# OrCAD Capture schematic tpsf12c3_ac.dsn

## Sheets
1 Page1: size C
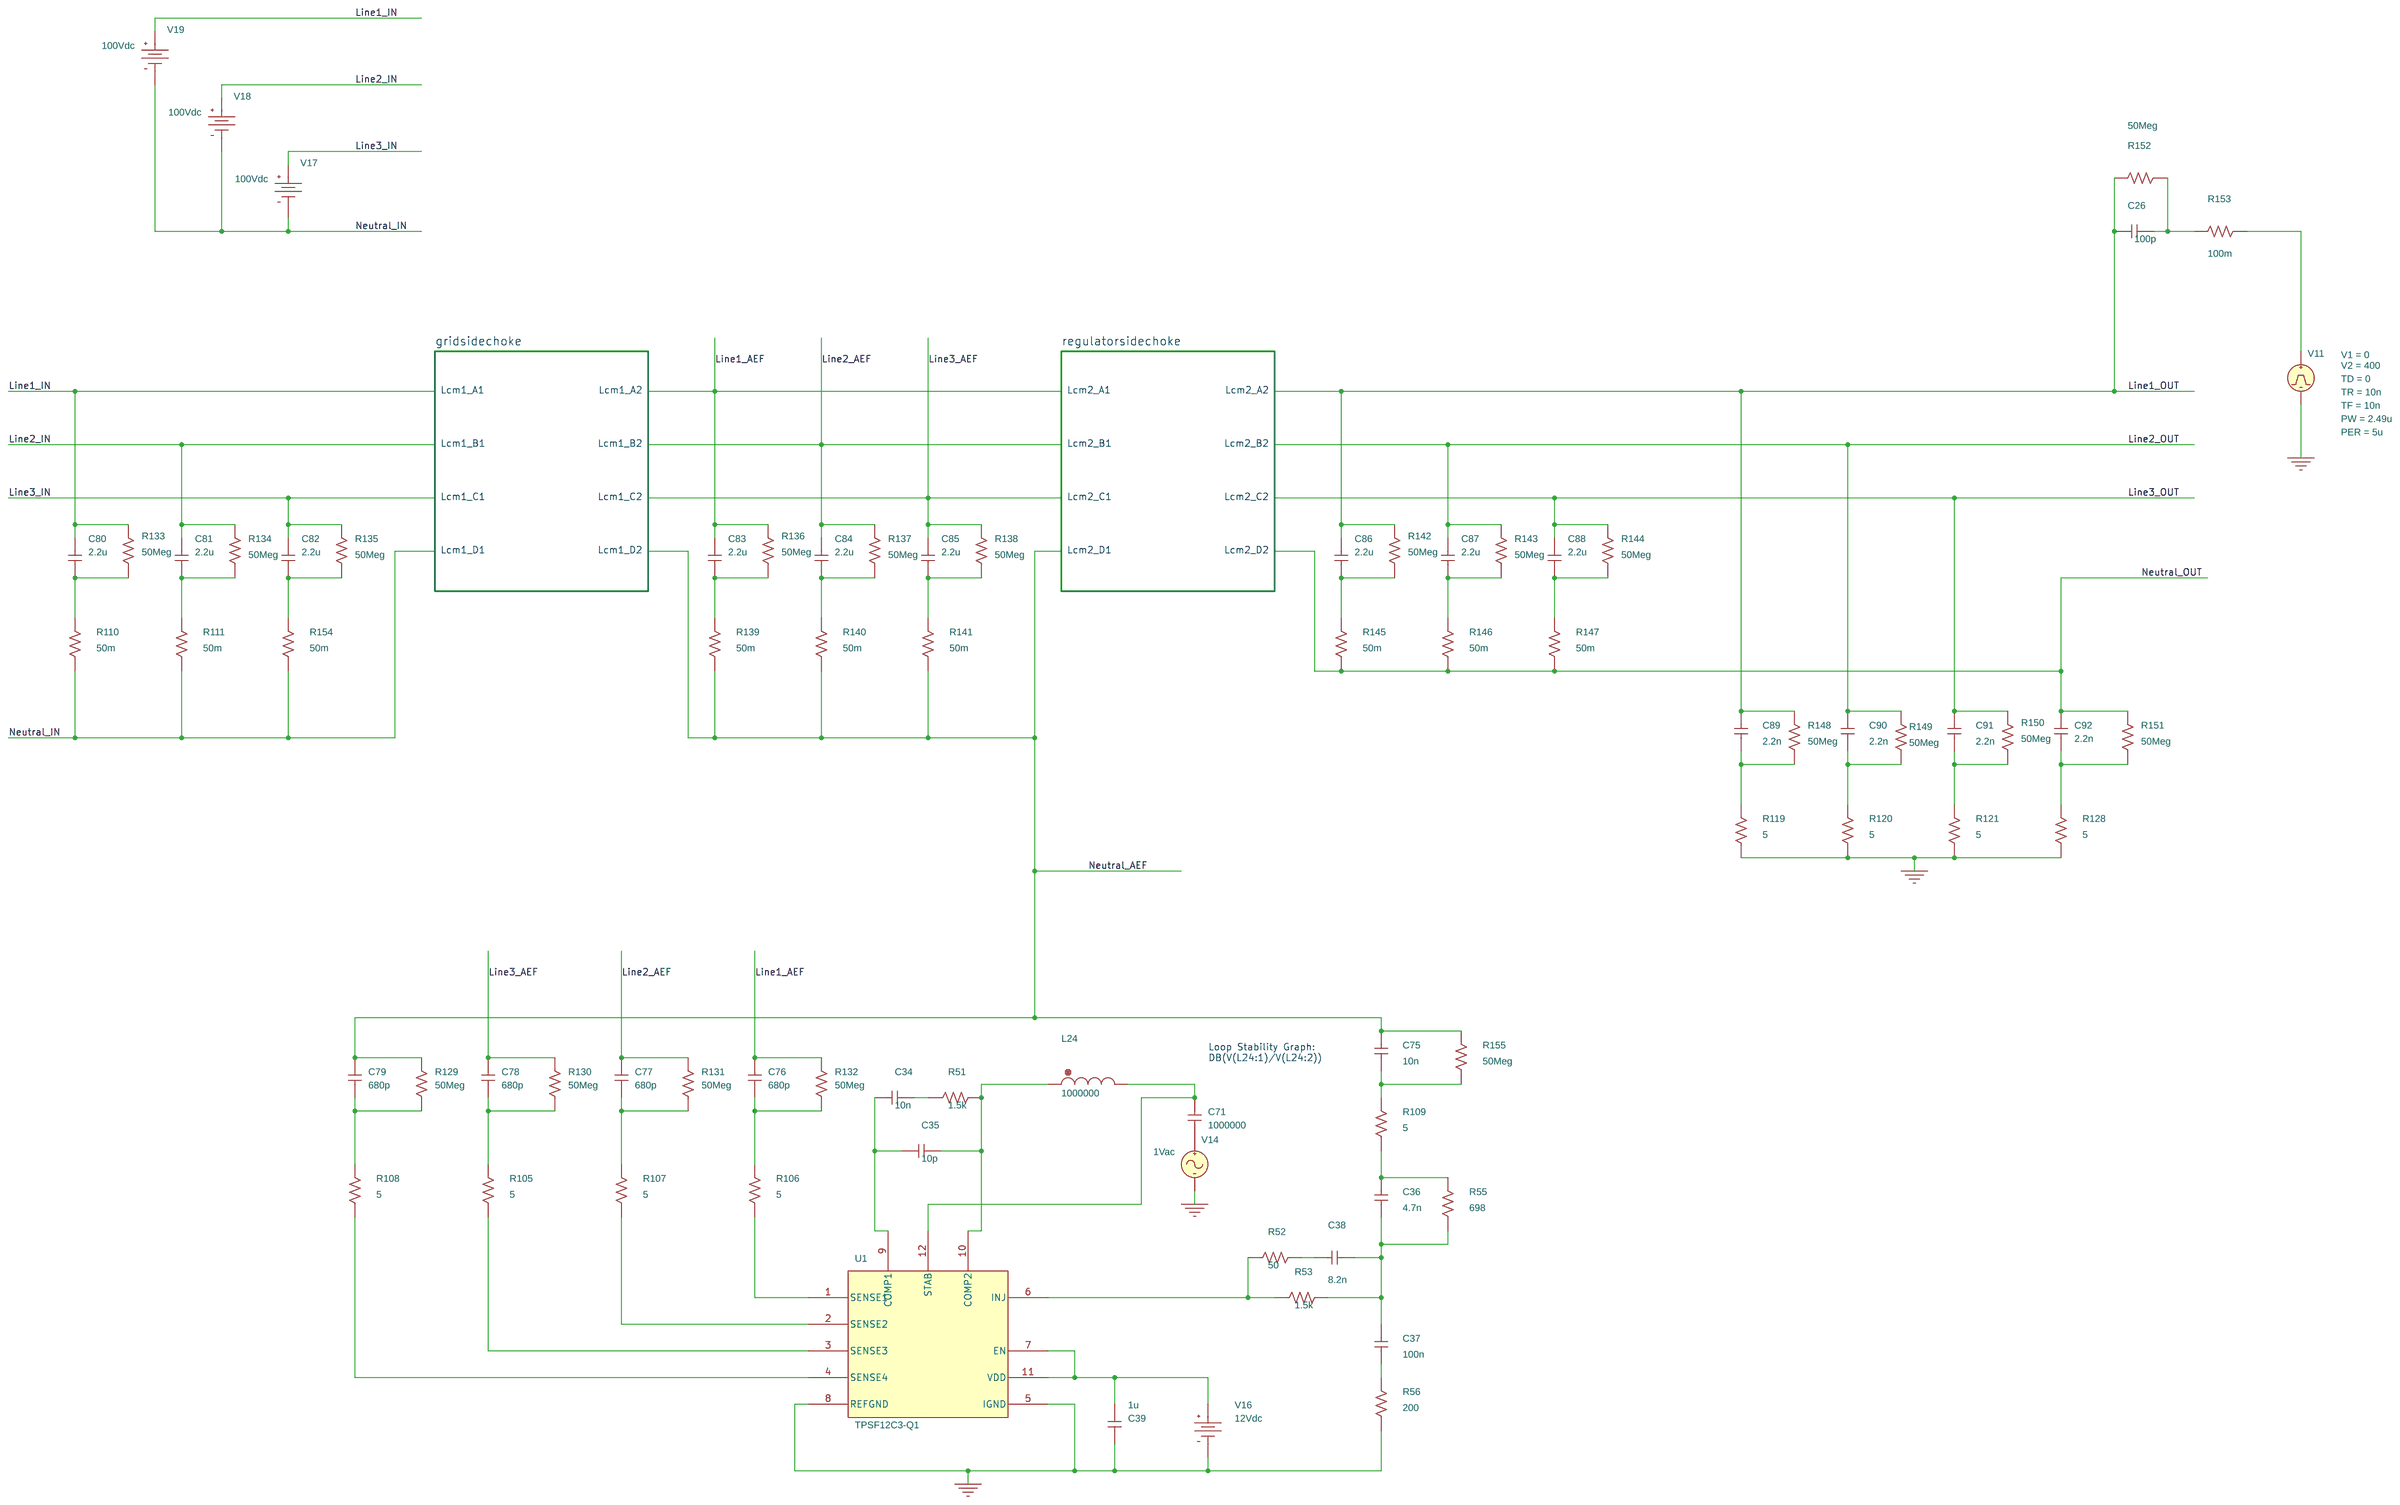
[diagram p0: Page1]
2 PAGE1 (2): size B; block gridsidechoke
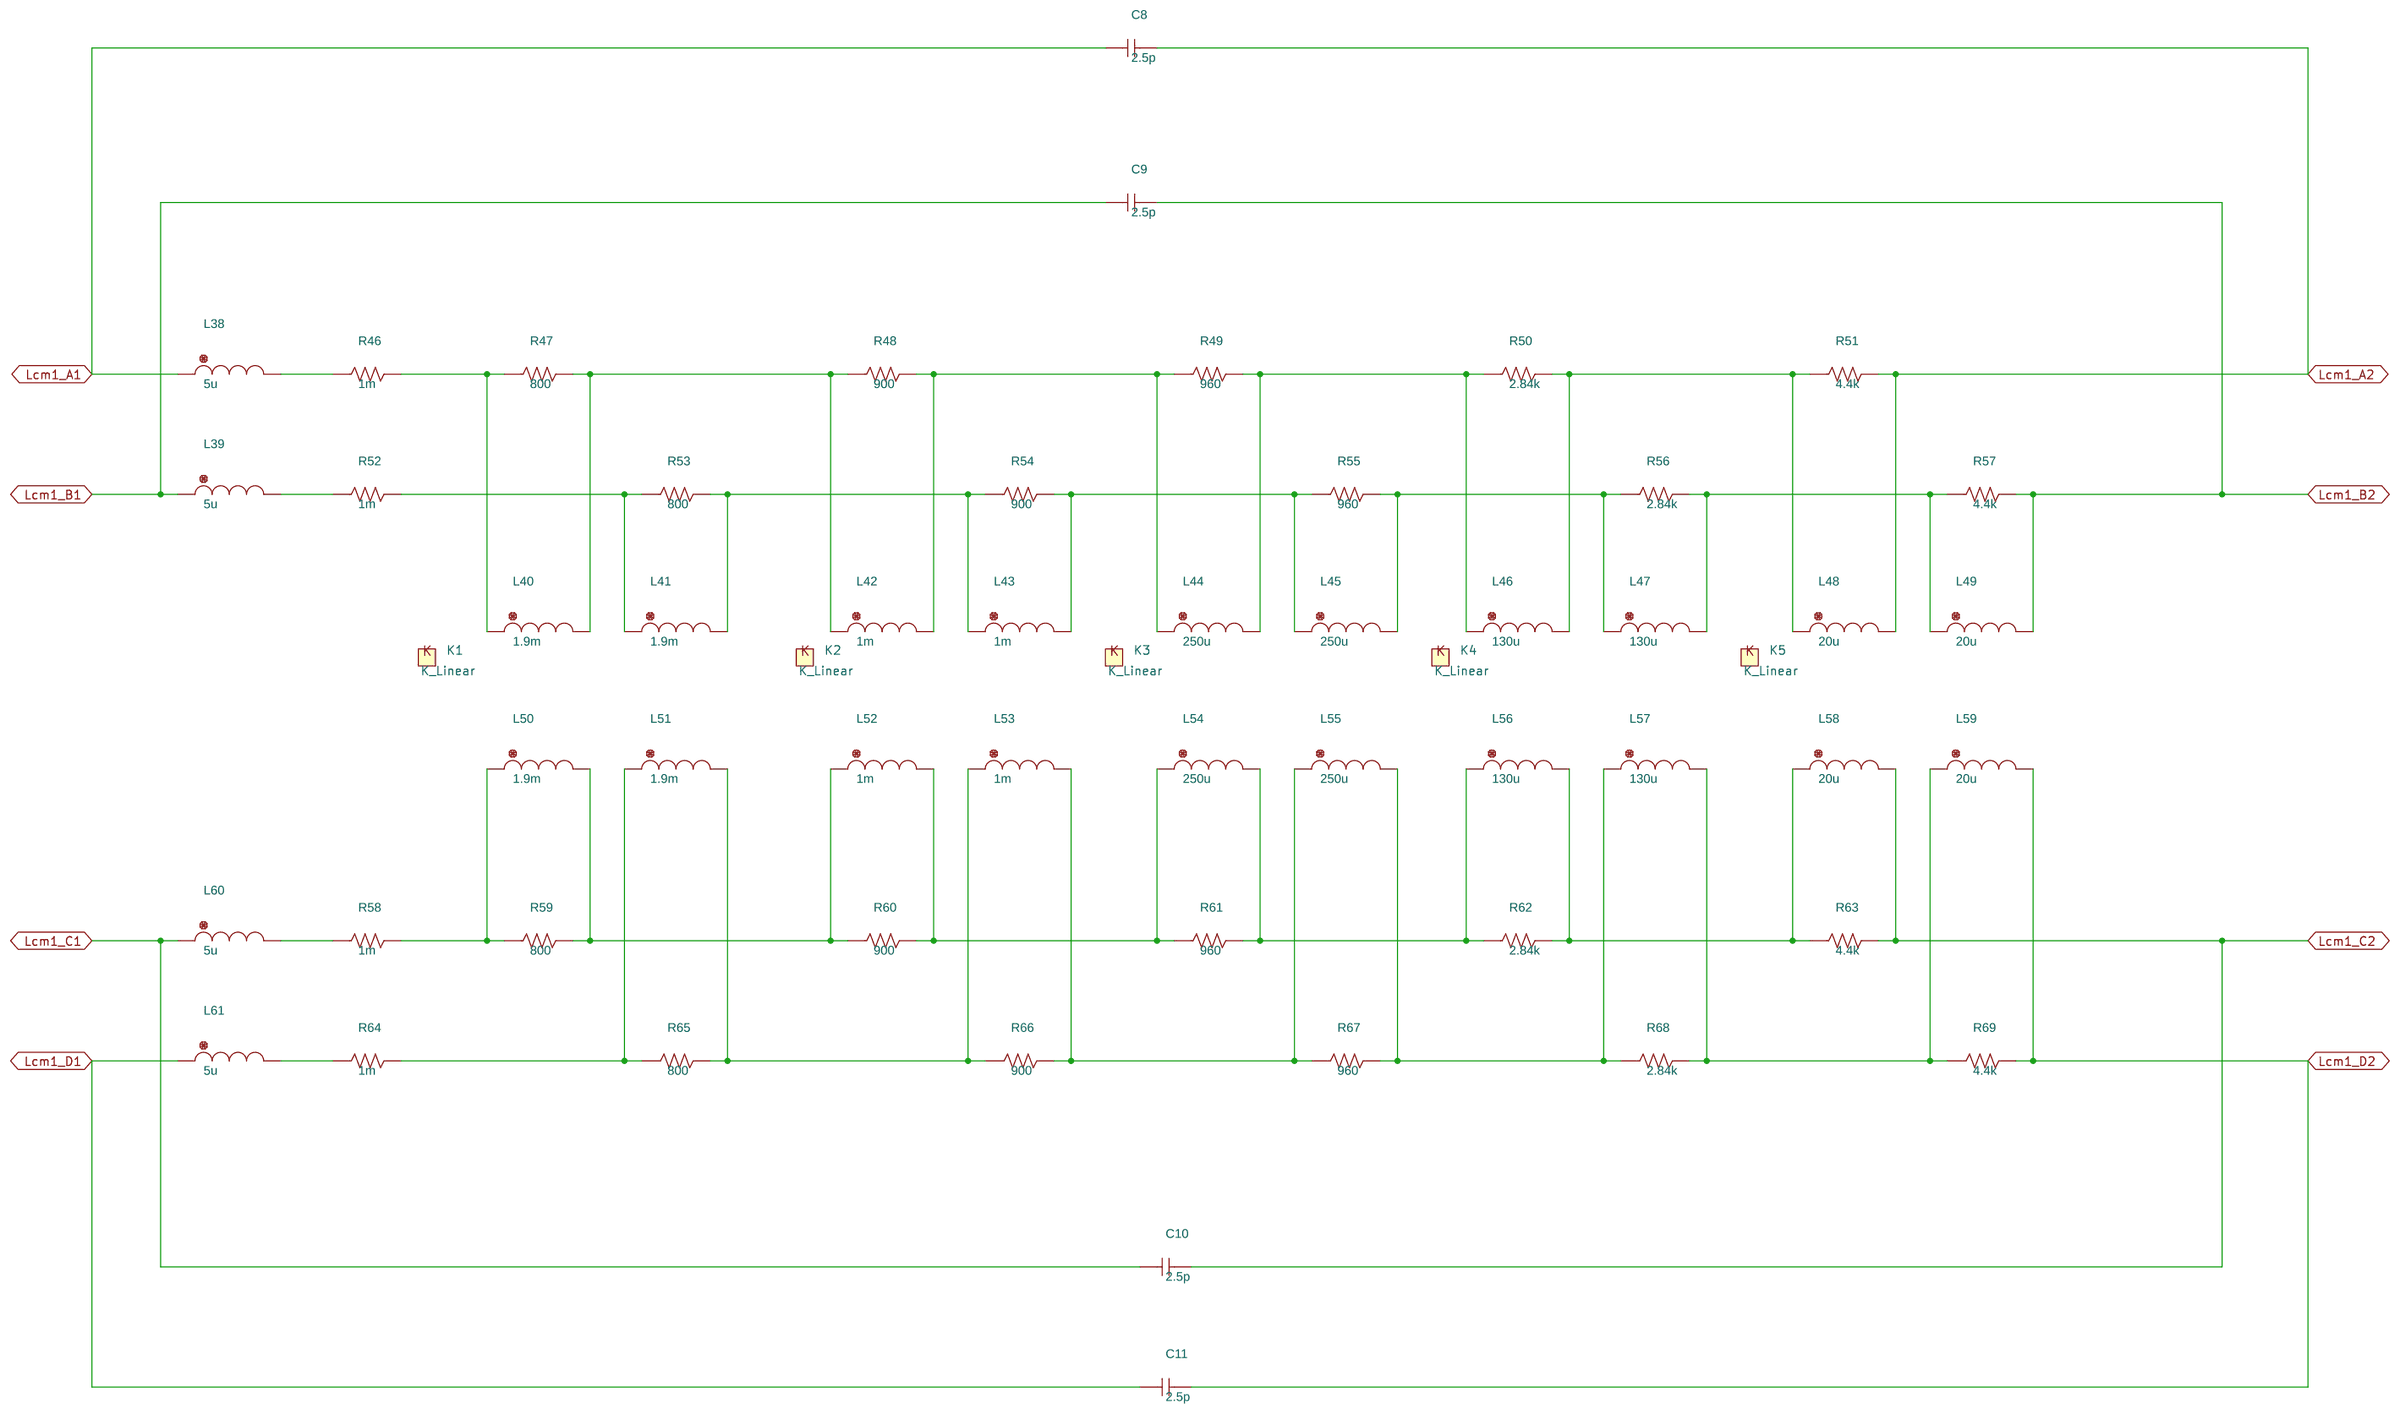
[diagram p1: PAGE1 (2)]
3 PAGE1 (3): size C; block regulatorsidechoke
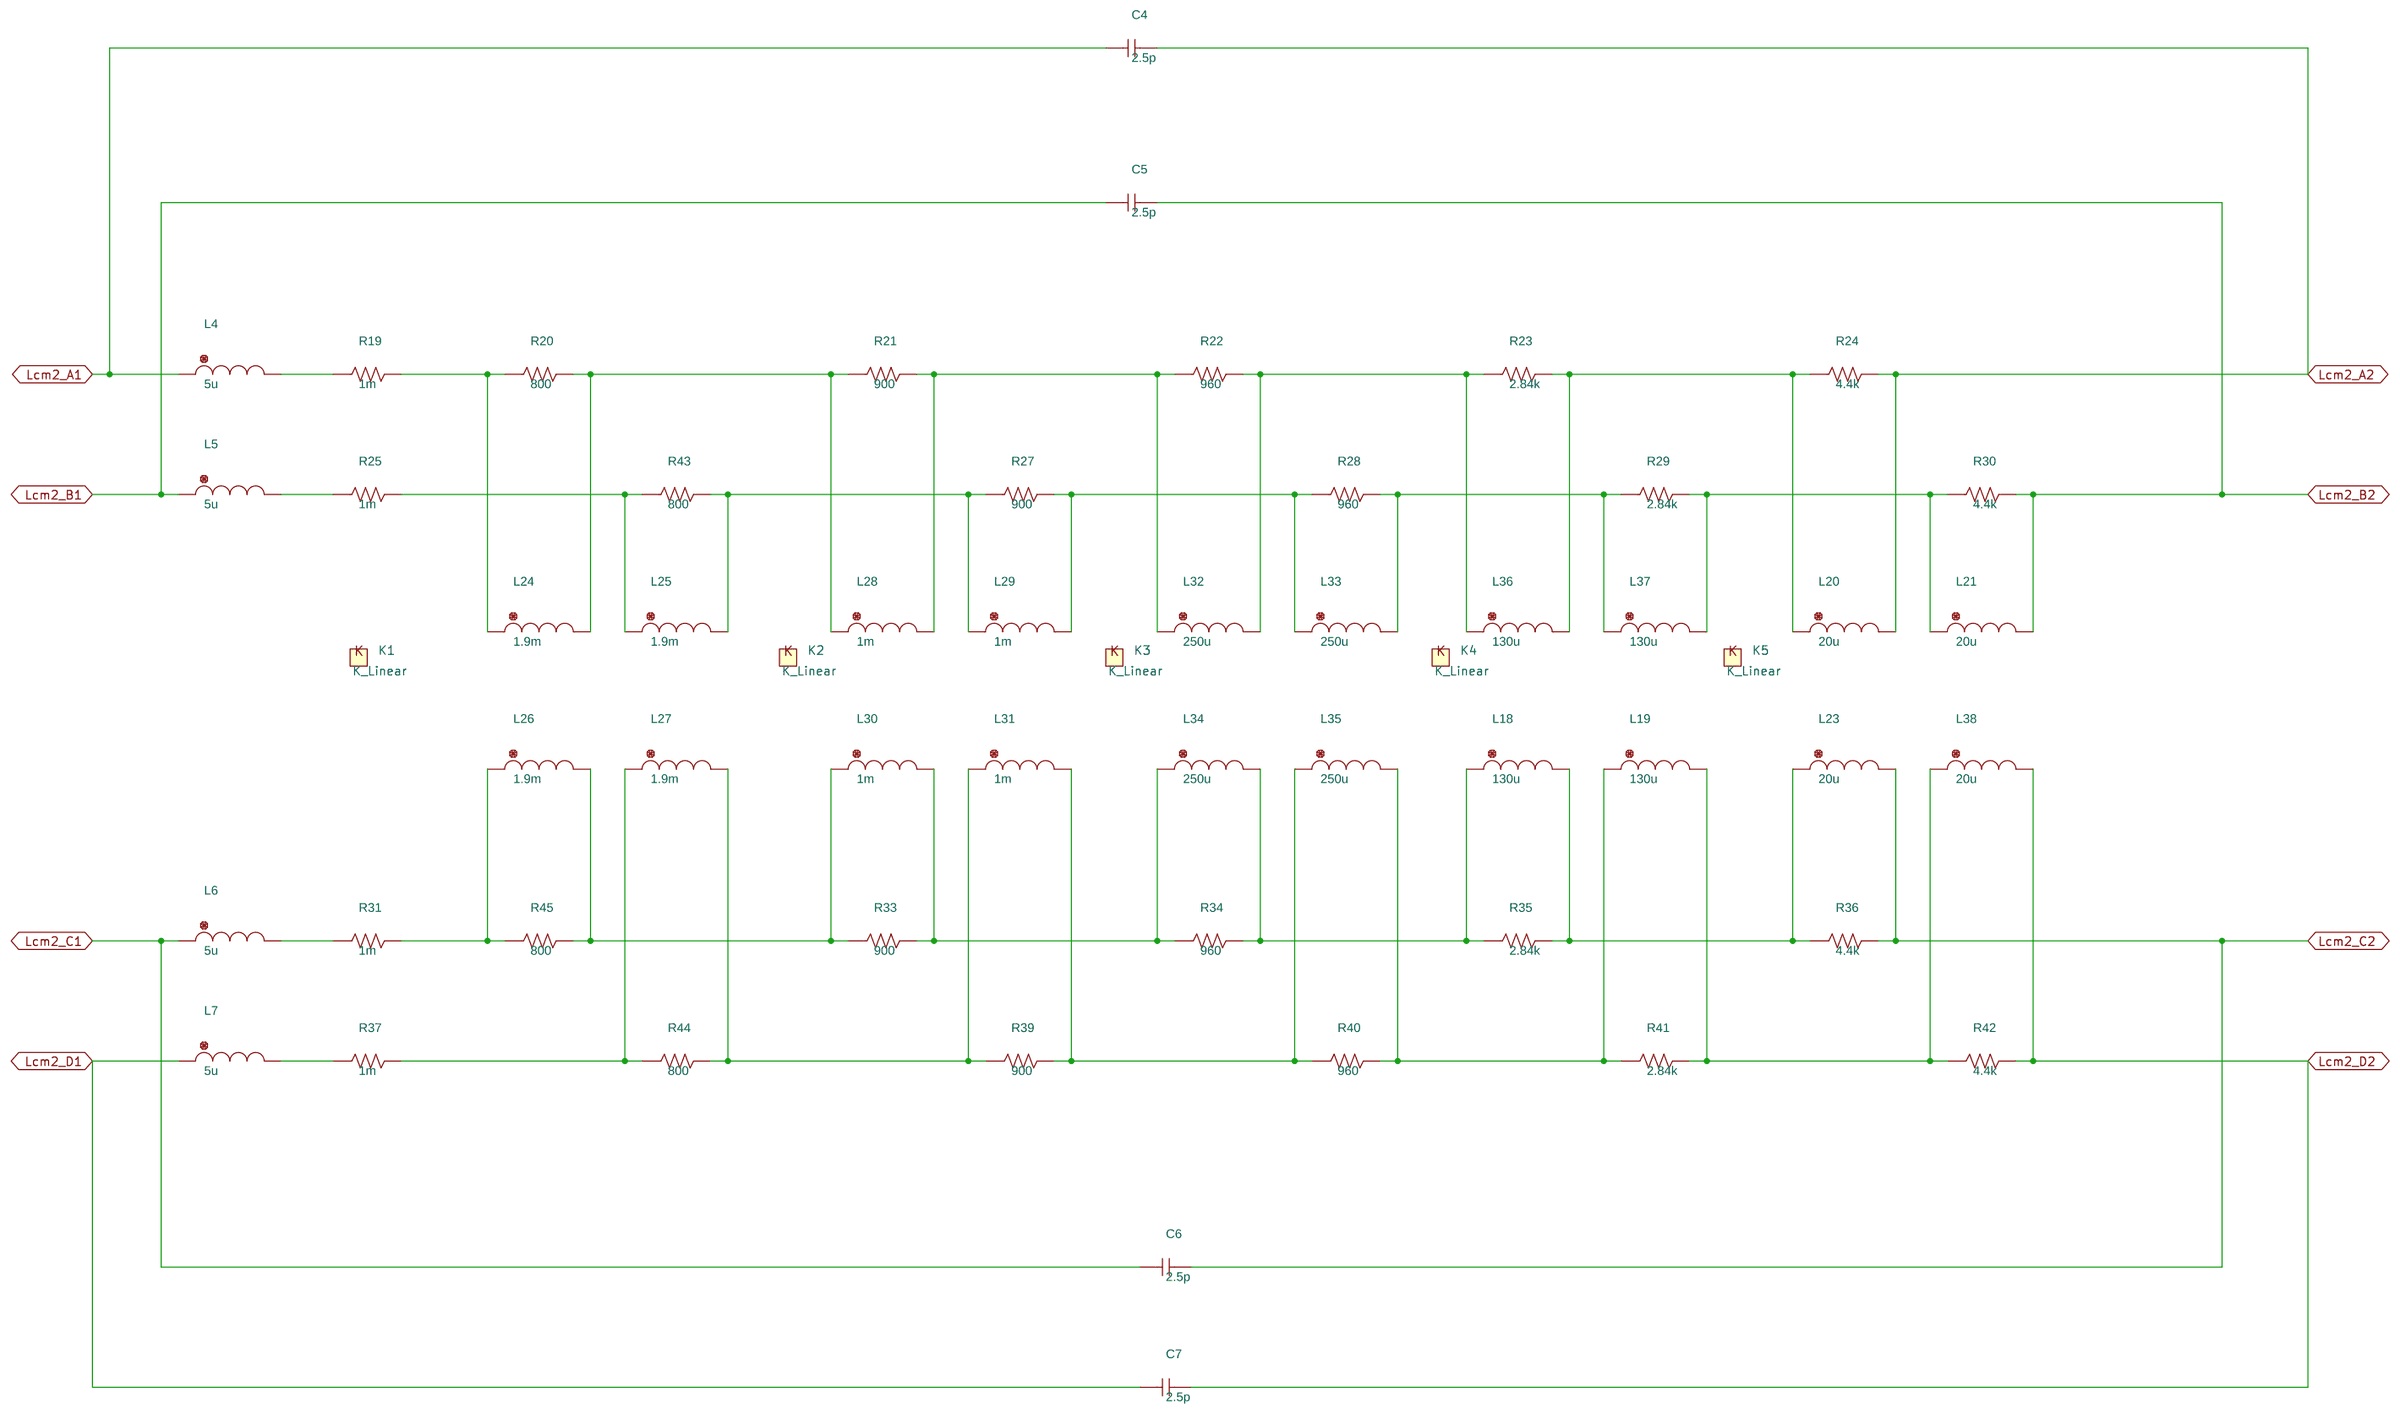
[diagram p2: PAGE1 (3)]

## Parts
sheet PAGE1 (2)
C8  2.5p  [cap196]
C9  2.5p  [cap196]
C10  2.5p  [cap196]
C11  2.5p  [cap196]
K1  K_Linear
K2  K_Linear
K3  K_Linear
K4  K_Linear
K5  K_Linear
L38  5u  [DISC350x175LS200x100034]
L38#2  5u  [DISC350x175LS200x100034]
L39  5u  [DISC350x175LS200x100034]
L40  1.9m  [DISC350x175LS200x100034]
L41  1.9m  [DISC350x175LS200x100034]
L42  1m  [DISC350x175LS200x100034]
L43  1m  [DISC350x175LS200x100034]
L44  250u  [DISC350x175LS200x100034]
L45  250u  [DISC350x175LS200x100034]
L46  130u  [DISC350x175LS200x100034]
L47  130u  [DISC350x175LS200x100034]
L48  20u  [DISC350x175LS200x100034]
L49  20u  [DISC350x175LS200x100034]
L50  1.9m  [DISC350x175LS200x100034]
L51  1.9m  [DISC350x175LS200x100034]
L52  1m  [DISC350x175LS200x100034]
L53  1m  [DISC350x175LS200x100034]
L54  250u  [DISC350x175LS200x100034]
L55  250u  [DISC350x175LS200x100034]
L56  130u  [DISC350x175LS200x100034]
L57  130u  [DISC350x175LS200x100034]
L58  20u  [DISC350x175LS200x100034]
L59  20u  [DISC350x175LS200x100034]
L60  5u  [DISC350x175LS200x100034]
L61  5u  [DISC350x175LS200x100034]
R46  1m  [AXRC05]
R47  800  [AXRC05]
R48  900  [AXRC05]
R49  960  [AXRC05]
R50  2.84k  [AXRC05]
R51  4.4k  [AXRC05]
R51#2  4.4k  [AXRC05]
R52  1m  [AXRC05]
R52#2  1m  [AXRC05]
R53  800  [AXRC05]
R53#2  800  [AXRC05]
R54  900  [AXRC05]
R55  960  [AXRC05]
R55#2  960  [AXRC05]
R56  2.84k  [AXRC05]
R56#2  2.84k  [AXRC05]
R57  4.4k  [AXRC05]
R58  1m  [AXRC05]
R59  800  [AXRC05]
R60  900  [AXRC05]
R61  960  [AXRC05]
R62  2.84k  [AXRC05]
R63  4.4k  [AXRC05]
R64  1m  [AXRC05]
R65  800  [AXRC05]
R66  900  [AXRC05]
R67  960  [AXRC05]
R68  2.84k  [AXRC05]
R69  4.4k  [AXRC05]
sheet PAGE1 (3)
C4  2.5p  [cap196]
C5  2.5p  [cap196]
C6  2.5p  [cap196]
C7  2.5p  [cap196]
L4  5u  [DISC350x175LS200x100034]
L5  5u  [DISC350x175LS200x100034]
L6  5u  [DISC350x175LS200x100034]
L7  5u  [DISC350x175LS200x100034]
L18  130u  [DISC350x175LS200x100034]
L19  130u  [DISC350x175LS200x100034]
L20  20u  [DISC350x175LS200x100034]
L21  20u  [DISC350x175LS200x100034]
L23  20u  [DISC350x175LS200x100034]
L24#2  1.9m  [DISC350x175LS200x100034]
L25  1.9m  [DISC350x175LS200x100034]
L26  1.9m  [DISC350x175LS200x100034]
L27  1.9m  [DISC350x175LS200x100034]
L28  1m  [DISC350x175LS200x100034]
L29  1m  [DISC350x175LS200x100034]
L30  1m  [DISC350x175LS200x100034]
L31  1m  [DISC350x175LS200x100034]
L32  250u  [DISC350x175LS200x100034]
L33  250u  [DISC350x175LS200x100034]
L34  250u  [DISC350x175LS200x100034]
L35  250u  [DISC350x175LS200x100034]
L36  130u  [DISC350x175LS200x100034]
L37  130u  [DISC350x175LS200x100034]
R19  1m  [AXRC05]
R20  800  [AXRC05]
R21  900  [AXRC05]
R22  960  [AXRC05]
R23  2.84k  [AXRC05]
R24  4.4k  [AXRC05]
R25  1m  [AXRC05]
R27  900  [AXRC05]
R28  960  [AXRC05]
R29  2.84k  [AXRC05]
R30  4.4k  [AXRC05]
R31  1m  [AXRC05]
R33  900  [AXRC05]
R34  960  [AXRC05]
R35  2.84k  [AXRC05]
R36  4.4k  [AXRC05]
R37  1m  [AXRC05]
R39  900  [AXRC05]
R40  960  [AXRC05]
R41  2.84k  [AXRC05]
R42  4.4k  [AXRC05]
R43  800  [AXRC05]
R44  800  [AXRC05]
R45  800  [AXRC05]
sheet Page1
C26  100p  [cap196]
C34  10n  [cap196]
C35  10p  [cap196]
C36  4.7n  [cap196]
C37  100n  [cap196]
C38  8.2n  [cap196]
C39  1u  [cap196]
C71  1000000  [cap196]
C75  10n  [cap196]
C76  680p  [cap196]
C77  680p  [cap196]
C78  680p  [cap196]
C79  680p  [cap196]
C80  2.2u  [cap196]
C81  2.2u  [cap196]
C82  2.2u  [cap196]
C83  2.2u  [cap196]
C84  2.2u  [cap196]
C85  2.2u  [cap196]
C86  2.2u  [cap196]
C87  2.2u  [cap196]
C88  2.2u  [cap196]
C89  2.2n  [cap196]
C90  2.2n  [cap196]
C91  2.2n  [cap196]
C92  2.2n  [cap196]
L24  1000000  [DISC350x175LS200x100034]
R105  5  [AXRC05]
R106  5  [AXRC05]
R107  5  [AXRC05]
R108  5  [AXRC05]
R109  5  [AXRC05]
R110  50m  [AXRC05]
R111  50m  [AXRC05]
R119  5  [AXRC05]
R120  5  [AXRC05]
R121  5  [AXRC05]
R128  5  [AXRC05]
R129  50Meg  [AXRC05]
R130  50Meg  [AXRC05]
R131  50Meg  [AXRC05]
R132  50Meg  [AXRC05]
R133  50Meg  [AXRC05]
R134  50Meg  [AXRC05]
R135  50Meg  [AXRC05]
R136  50Meg  [AXRC05]
R137  50Meg  [AXRC05]
R138  50Meg  [AXRC05]
R139  50m  [AXRC05]
R140  50m  [AXRC05]
R141  50m  [AXRC05]
R142  50Meg  [AXRC05]
R143  50Meg  [AXRC05]
R144  50Meg  [AXRC05]
R145  50m  [AXRC05]
R146  50m  [AXRC05]
R147  50m  [AXRC05]
R148  50Meg  [AXRC05]
R149  50Meg  [AXRC05]
R150  50Meg  [AXRC05]
R151  50Meg  [AXRC05]
R152  50Meg  [AXRC05]
R153  100m  [AXRC05]
R154  50m  [AXRC05]
R155  50Meg  [AXRC05]
U1  TPSF12C3-Q1
V11  VPULSE
V14  VAC
V16  VDC
V17  VDC
V18  VDC
V19  VDC

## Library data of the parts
C4-C11 C26 C34-C36 C38 C39 C75-C92 = C
K1 = K_Linear: L1: L40; L2: L41; L3: L50; L4: L51
K2 = K_Linear: L1: L42; L2: L43; L3: L52; L4: L53
K3 = K_Linear: L1: L44; L2: L45; L3: L54; L4: L55
K4 = K_Linear: L1: L46; L2: L47; L3: L56; L4: L57
K5 = K_Linear: L1: L48; L2: L49; L3: L58; L4: L59
L4-L7 L18-L21 L23 L24 L24#2 L25-L38 L38#2 L39-L61 = L
R19-R25 R27-R31 R33-R37 R39-R51 R51#2 R52 R52#2 R53 R53#2 R54 R55 R55#2 R56 R56#2 R57-R69 R105-R111 R119-R121 R128-R155 = R
C37 = C: IC: 6
C71 = C: IC: 0
U1 = TPSF12C3-Q1
V11 = VPULSE: PER: 5u; PW: 2.49u; TD: 0; TF: 10n; TR: 10n; V1: 0; V2: 400
V14 = VAC: ACMAG: 1Vac
V16 = VDC: DC: 12Vdc
V17-V19 = VDC: DC: 100Vdc

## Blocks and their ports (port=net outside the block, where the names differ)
regulatorsidechoke = schematic regulatorsidechoke, on sheet Page1: Lcm2_A1=Line1_AEF, Lcm2_A2=Line1_OUT, Lcm2_B1=Line2_AEF, Lcm2_B2=Line2_OUT, Lcm2_C1=Line3_AEF, Lcm2_C2=Line3_OUT, Lcm2_D1=Neutral_AEF, Lcm2_D2=Neutral_OUT
gridsidechoke = schematic gridsidechoke, on sheet Page1: Lcm1_A1=Line1_IN, Lcm1_A2=Line1_AEF, Lcm1_B1=Line2_IN, Lcm1_B2=Line2_AEF, Lcm1_C1=Line3_IN, Lcm1_C2=Line3_AEF, Lcm1_D1=Neutral_IN, Lcm1_D2=Neutral_AEF

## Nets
0: C39.2 R56.1 R119.1 R120.1 R121.1 R128.1 U1.5(IGND) U1.8(REFGND) V11.2(-) V14.2(-) V16.1(-)
Line1_AEF: C4.1 C8.2 C76.2 C83.2 L4.1 L48.2 R51#2.2 R132.2 R136.2
Line1_IN: C8.1 C80.2 L38#2.1 R133.2 V19.0(+)
Line1_OUT: C4.2 C26.1 C86.2 C89.2 L20.2 R24.2 R142.2 R148.2 R152.2
Line2_AEF: C5.1 C9.2 C77.2 C84.2 L5.1 L49.2 R57.2 R131.2 R137.2
Line2_IN: C9.1 C81.2 L39.1 R134.2 V18.0(+)
Line2_OUT: C5.2 C87.2 C90.2 L21.2 R30.2 R143.2 R149.2
Line3_AEF: C6.1 C10.2 C78.2 C85.2 L6.1 L58.2 R63.2 R130.2 R138.2
Line3_IN: C10.1 C82.2 L60.1 R135.2 V17.0(+)
Line3_OUT: C6.2 C88.2 C91.2 L23.2 R36.2 R144.2 R150.2
Neutral_AEF: C7.1 C11.2 C75.2 C79.2 L7.1 L59.2 R69.2 R129.2 R139.1 R140.1 R141.1 R155.2
Neutral_IN: C11.1 L61.1 R110.1 R111.1 R154.1 V17.1(-) V18.1(-) V19.1(-)
Neutral_OUT: C7.2 C92.1 L38.2 R42.2 R145.1 R146.1 R147.1 R151.2
gridsidechoke/N25300: L38#2.2 R46.1
gridsidechoke/N25306: L40.1 R46.2 R47.1
gridsidechoke/N25320: L40.2 L42.1 R47.2 R48.1
gridsidechoke/N25342: L42.2 L44.1 R48.2 R49.1
gridsidechoke/N25364: L44.2 L46.1 R49.2 R50.1
gridsidechoke/N25386: L46.2 L48.1 R50.2 R51#2.1
gridsidechoke/N25584: L39.2 R52#2.1
gridsidechoke/N25590: L41.1 R52#2.2 R53#2.1
gridsidechoke/N25604: L41.2 L43.1 R53#2.2 R54.1
gridsidechoke/N25626: L43.2 L45.1 R54.2 R55#2.1
gridsidechoke/N25648: L45.2 L47.1 R55#2.2 R56#2.1
gridsidechoke/N25670: L47.2 L49.1 R56#2.2 R57.1
gridsidechoke/N26188: L50.1 R58.2 R59.1
gridsidechoke/N26194: L50.2 L52.1 R59.2 R60.1
gridsidechoke/N26198: L51.1 R64.2 R65.1
gridsidechoke/N26204: L51.2 L53.1 R65.2 R66.1
gridsidechoke/N26214: L52.2 L54.1 R60.2 R61.1
gridsidechoke/N26222: L53.2 L55.1 R66.2 R67.1
gridsidechoke/N26232: L54.2 L56.1 R61.2 R62.1
gridsidechoke/N26240: L55.2 L57.1 R67.2 R68.1
gridsidechoke/N26250: L56.2 L58.1 R62.2 R63.1
gridsidechoke/N26258: L57.2 L59.1 R68.2 R69.1
gridsidechoke/N26450: L60.2 R58.1
gridsidechoke/N26706: L61.2 R64.1
N210526: C26.2 R152.1 R153.2
N210582: R153.1 V11.1(+)
N211300: C80.1 R110.2 R133.1
N211310: C81.1 R111.2 R134.1
N211320: C82.1 R135.1 R154.2
N211330: C83.1 R136.1 R139.2
N211340: C84.1 R137.1 R140.2
N211350: C85.1 R138.1 R141.2
N211360: C86.1 R142.1 R145.2
N211370: C87.1 R143.1 R146.2
N211380: C88.1 R144.1 R147.2
N211850: C89.1 R119.2 R148.1
N211854: C90.1 R120.2 R149.1
N211858: C91.1 R121.2 R150.1
N211862: C92.2 R128.2 R151.1
N212286: C75.1 R109.2 R155.1
N212300: C79.1 R108.2 R129.1
N212304: C78.1 R105.2 R130.1
N212308: C77.1 R107.2 R131.1
N212314: C76.1 R106.2 R132.1
N212400: C34.1 C35.1 U1.9(COMP1)
N212406: C34.2 R51.1
N212412: C35.2 L24.1 R51.2 U1.10(COMP2)
N212456: C36.2 R55.2 R109.1
N212616: R108.1 U1.4(SENSE4)
N212620: R105.1 U1.3(SENSE3)
N212624: R107.1 U1.2(SENSE2)
N212628: R106.1 U1.1(SENSE1)
N212698: C36.1 C37.2 C38.1 R53.2 R55.1
N212764: R52.1 R53.1 U1.6(INJ)
N212768: C38.2 R52.2
N212844: C39.1 U1.7(EN) U1.11(VDD) V16.0(+)
N212882: C37.1 R56.2
N214754: C71.2 L24.2 U1.12(STAB)
N237404: C71.1 V14.1(+)
regulatorsidechoke/N33650: L4.2 R19.1
regulatorsidechoke/N33656: L24#2.1 R19.2 R20.1
regulatorsidechoke/N33670: L24#2.2 L28.1 R20.2 R21.1
regulatorsidechoke/N33692: L28.2 L32.1 R21.2 R22.1
regulatorsidechoke/N33714: L32.2 L36.1 R22.2 R23.1
regulatorsidechoke/N33736: L20.1 L36.2 R23.2 R24.1
regulatorsidechoke/N33940: L5.2 R25.1
regulatorsidechoke/N33946: L25.1 R25.2 R43.1
regulatorsidechoke/N33960: L25.2 L29.1 R27.1 R43.2
regulatorsidechoke/N33982: L29.2 L33.1 R27.2 R28.1
regulatorsidechoke/N34004: L33.2 L37.1 R28.2 R29.1
regulatorsidechoke/N34026: L21.1 L37.2 R29.2 R30.1
regulatorsidechoke/N34584: L26.1 R31.2 R45.1
regulatorsidechoke/N34590: L26.2 L30.1 R33.1 R45.2
regulatorsidechoke/N34594: L27.1 R37.2 R44.1
regulatorsidechoke/N34600: L27.2 L31.1 R39.1 R44.2
regulatorsidechoke/N34610: L30.2 L34.1 R33.2 R34.1
regulatorsidechoke/N34618: L31.2 L35.1 R39.2 R40.1
regulatorsidechoke/N34628: L18.1 L34.2 R34.2 R35.1
regulatorsidechoke/N34636: L19.1 L35.2 R40.2 R41.1
regulatorsidechoke/N34646: L18.2 L23.1 R35.2 R36.1
regulatorsidechoke/N34654: L19.2 L38.1 R41.2 R42.1
regulatorsidechoke/N34856: L6.2 R31.1
regulatorsidechoke/N35112: L7.2 R37.1

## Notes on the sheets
sheet 1
- Loop Stability Graph:
  DB(V(L24:1)/V(L24:2))
